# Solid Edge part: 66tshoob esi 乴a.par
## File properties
Author: KULL
Template: Iso Metric Part.par
Last saved by: KULL
Revision: 13
Application: Solid Edge
Accuracy: 0,990
Face Style: Model Default
Fill Style: Normal
Coef. of Thermal Exp: 0.0
Thermal Conductivity: 0.0
Specific Heat: 0.0
Modulus of Elasticity: 0.0
Poisson's Ratio: 0.0
Yield Stress: 0.0
Ultimate Stress: 0.0
Elongation: 0.0
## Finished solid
Body 1: solid body, 171 faces, 380 edges, 210 vertices.
  Faces by surface: cylinder 67, torus 49, plane 27, blend 20, sphere 8
  Edges by curve: circle 216, line 124, intersection 40
Bounding box of the edges (mm; curved faces can reach further): 58.000 x 73.653 x 19.599, from (-29, 40, 42.2122) to (29, 113.6532, 61.811).
Cylindrical faces by radius (mm): R0.4 x11, R1 x39, R2.5 x2, R3.6473 x2, R5 x2, R5.8473 x2, R7.7684 x1, R20.1477 x2, R22.3477 x2, R36.2904 x2, R38.4904 x2
Toroidal faces (ring radius, tube radius in mm): R1.4 r0.4 x6, R3.8777 r1 x1, R4 r1 x4, R4.141 r1 x2, R4.2624 r1 x2, R4.6473 r1 x4, R5.4473 r0.4 x2, R6 r1 x4, R6.8473 r1 x2, R6.9282 r2 x2, R7.3684 r0.4 x1, R7.746 r2 x2, R8.7684 r1 x1, R19.1477 r1 x2, R20.5477 r0.4 x2, R21.3477 r1 x4, R37.2904 r1 x4, R38.0904 r0.4 x2, R39.4904 r1 x2
Spherical faces by radius (mm): R1 x6, R4 x1, R6 x1
Planar faces by outward normal: +x 6, -x 6, oblique 15
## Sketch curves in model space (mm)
circle centre (29, 45, 56.811) radius 2.5
line (-24.5604, 63.7435, 54.659) -> (-20.7385, 63.7435, 54.659)
line (0, 27.8239, 46) -> (0, 109, 46)
arc centre (20.0281, 62.9924, 53.7717) radius 36.2904 from (-16.2623, 62.9924, 53.7717) through (-14.6082, 73.6725, 51.9676) to (-9.7966, 83.3791, 50.3279)
line (-16.2623, 62.9924, 53.7717) -> (-16.2623, 51.5164, 55.7102)
line (-27.9903, 51.5164, 55.7102) -> (-16.2623, 51.5164, 55.7102)
line (-27.9903, 51.5164, 55.7102) -> (-27.9903, 66.9926, 53.096)
arc centre (-5.6427, 66.9926, 53.096) radius 22.3477 from (-27.9903, 66.9926, 53.096) through (-26.7164, 74.3262, 51.8572) to (-23.0398, 80.8236, 50.7596)
line (-3.4951, 104.7257, 46.722) -> (-23.0398, 80.8236, 50.7596)
arc centre (0, 109, 46) radius 5.5684 from (3.4951, 104.7257, 46.722) through (-0.1643, 103.5118, 46.9271) to (-3.4951, 104.7257, 46.722)
line (3.4951, 104.7257, 46.722) -> (23.0398, 80.8236, 50.7596)
arc centre (5.6427, 66.9926, 53.096) radius 22.3477 from (27.9903, 66.9926, 53.096) through (26.7164, 74.3262, 51.8572) to (23.0398, 80.8236, 50.7596)
line (27.9903, 51.5164, 55.7102) -> (27.9903, 66.9926, 53.096)
line (27.9903, 51.5164, 55.7102) -> (16.2623, 51.5164, 55.7102)
line (16.2623, 62.9924, 53.7717) -> (16.2623, 51.5164, 55.7102)
arc centre (-20.0281, 62.9924, 53.7717) radius 36.2904 from (16.2623, 62.9924, 53.7717) through (14.6082, 73.6725, 51.9676) to (9.7966, 83.3791, 50.3279)
line (3.4996, 92.3358, 48.8149) -> (9.7966, 83.3791, 50.3279)
arc centre (0.5021, 90.2869, 49.161) radius 3.6473 from (3.4996, 92.3358, 48.8149) through (2.1938, 93.473, 48.6229) to (0.5021, 93.8832, 48.5536)
line (0.5021, 93.8832, 48.5536) -> (0, 93.8832, 48.5536)
line (-0.5021, 93.8832, 48.5536) -> (0, 93.8832, 48.5536)
arc centre (-0.5021, 90.2869, 49.161) radius 3.6473 from (-3.4996, 92.3358, 48.8149) through (-2.1938, 93.473, 48.6229) to (-0.5021, 93.8832, 48.5536)
line (-3.4996, 92.3358, 48.8149) -> (-9.7966, 83.3791, 50.3279)
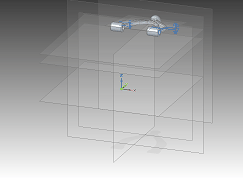
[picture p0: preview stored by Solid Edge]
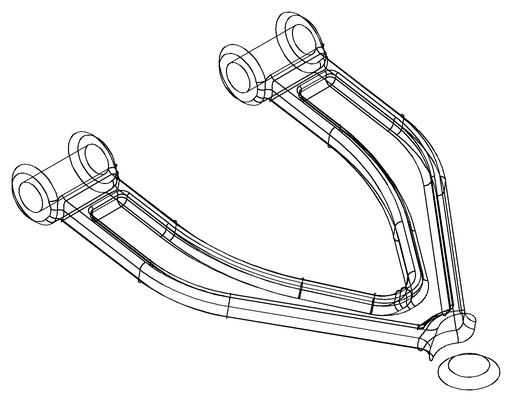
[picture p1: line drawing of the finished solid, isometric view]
